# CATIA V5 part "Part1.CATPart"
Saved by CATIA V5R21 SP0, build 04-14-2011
Part number: Part1
Bounding box of the stored display mesh (mm): x -100 to 100, y -50 to 50, z -20 to 20
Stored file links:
  D:\CATIA V5R21 E-RESOURCES\CATIA-V5R21\catia-v5r21-prt\c16-catia-v5r20-prt\Prismatic Joint-(Fig16-14)\CAT_V5R21_Part1.CATPart
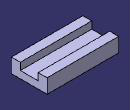
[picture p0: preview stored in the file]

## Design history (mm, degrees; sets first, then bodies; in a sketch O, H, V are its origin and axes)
Body1 (main body)
  Sketch1 on yz-plane, origin (0, 0, 0), H (0, 1, 0), V (0, 0, 1)
    line L1 (50, 20) -> (50, -20)
    line L2 (50, -20) -> (-50, -20)
    line L3 (-50, -20) -> (-50, 20)
    point P1 (50, 20)
    point P4 (-50, 20)
    point P5 (0, 8.2157)
    line L4 (25, 20) -> (25, 0)
    line L5 (25, 0) -> (-25, 0)
    line L6 (-25, 0) -> (-25, 20)
    line L7 (-25, 20) -> (-50, 20)
    point P10 (-50, 20)
    line L8 (25, 20) -> (50, 20)
    point P11 (50, 20)
    distance V L3 = 50
    distance L6 V = 25
    length L5 = 50
    distance L2 L5 = 20
    length L3 = 40
    vertical: L1 V, L3 V, L4 V, L6 V
    horizontal: L2 H, L5 H, L7 H, L8 H
    equidistance: L1 L3 O, L4 L6 P5
    coincidence: P4 P10, P11 L1, P11 P1, L7 L8, H L5
  Pad1: profile Sketch1, direction (1, 0, 0), length 100, mirrored extent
